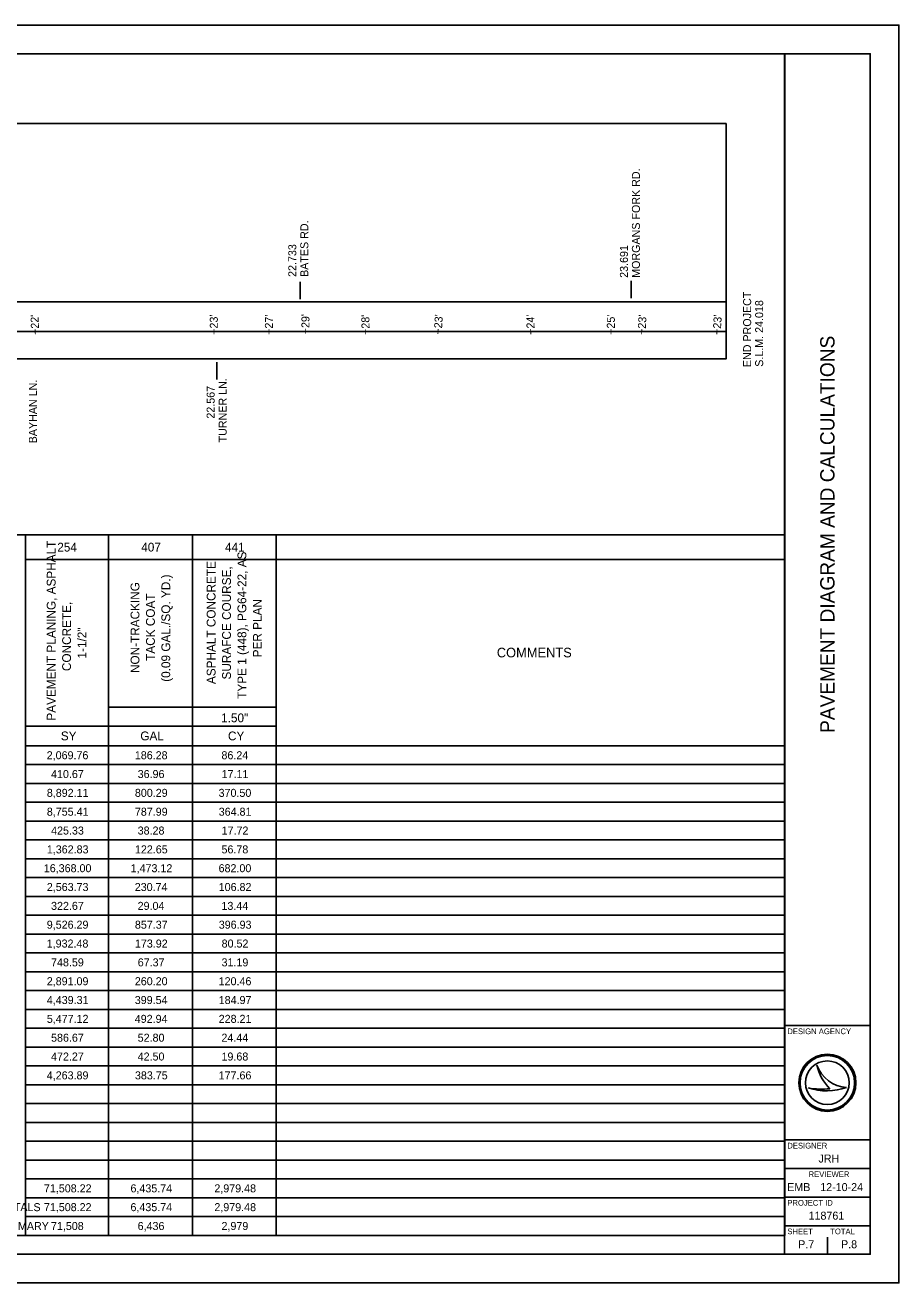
# Model space of a CAD drawing. Extents: x 0 to 34, y 0 to 22.
# Drawn here: x 18.72 to 34, y 0 to 22 of the extents above; entities that cross this region are included whole.
import ezdxf

# ---------------------------------------------------------------- set-up
doc = ezdxf.new("R2010")
doc.units = 0
for name, color, linetype in [('Default', 7, 'Continuous'), ('SH_Border', 7, 'Continuous'), ('SH_Cut_Line', 7, 'Continuous'), ('SH_Data', 7, 'Continuous'), ('SH_Text', 7, 'Continuous')]:
    doc.layers.add(name, color=color, linetype=linetype)

msp = doc.modelspace()

# ---------------------------------------------------------------- linework, layer by layer
at = {"layer": 'Default'}
for p, q in [((1.5, 21.5), (32.004, 21.5)), ((32.004, 21.5), (32.004, 0.829)), ((2.554, 20.282), (30.979, 20.282)), ((30.979, 19.16), (30.979, 20.282)), ((30.979, 20.282), (30.979, 17.16)), ((23.527, 17.209), (23.527, 17.509)), ((29.316, 17.225), (29.316, 17.525)), ((30.979, 17.16), (30.979, 16.161)), ((2.564, 16.643), (30.989, 16.64)), ((22.072, 16.104), (22.072, 15.804)), ((15.802, 13.084), (18.723, 13.084)), ((18.701, 13.084), (32.004, 13.084)), ((18.723, 13.084), (18.723, 0.829)), ((20.178, 13.084), (20.178, 0.829)), ((21.644, 13.084), (21.644, 0.829)), ((23.109, 13.084), (23.109, 0.829)), ((18.723, 12.655), (32.004, 12.655)), ((20.178, 10.069), (23.109, 10.069)), ((18.723, 9.74), (23.109, 9.74)), ((18.723, 9.394), (32.004, 9.394)), ((18.723, 9.065), (32.004, 9.065)), ((18.723, 8.735), (32.004, 8.735)), ((18.723, 8.406), (32.004, 8.406)), ((18.723, 8.076), (32.004, 8.076)), ((18.723, 7.747), (32.004, 7.747)), ((18.723, 7.418), (32.004, 7.418)), ((18.723, 7.088), (32.004, 7.088)), ((18.723, 6.759), (32.004, 6.759)), ((18.723, 6.429), (32.004, 6.429)), ((18.723, 6.1), (32.004, 6.1)), ((18.723, 5.771), (32.004, 5.771)), ((18.723, 5.441), (32.004, 5.441)), ((18.723, 5.112), (32.004, 5.112)), ((18.723, 4.782), (32.004, 4.782)), ((18.723, 4.453), (32.004, 4.453)), ((18.723, 4.124), (32.004, 4.124)), ((18.723, 3.794), (32.004, 3.794)), ((18.723, 3.465), (32.004, 3.465)), ((18.723, 3.135), (32.004, 3.135)), ((18.723, 2.806), (32.004, 2.806)), ((18.723, 2.476), (32.004, 2.476)), ((18.723, 2.147), (32.004, 2.147)), ((18.723, 1.818), (32.004, 1.818)), ((18.723, 1.488), (32.004, 1.488)), ((18.723, 1.159), (32.004, 1.159)), ((1.5, 0.829), (18.723, 0.829)), ((18.701, 0.829), (32.004, 0.829))]:
    msp.add_line(p, q, dxfattribs=at)
msp.add_lwpolyline([(30.979, 17.16), (2.554, 17.16), (2.554, 16.161), (30.979, 16.161)], close=True, dxfattribs=at)
at = {"layer": 'SH_Border'}
for p, q in [((32, 0.5), (32, 21.5)), ((32, 4.5), (33.5, 4.5)), ((32, 2.5), (33.5, 2.5)), ((32, 2), (33.5, 2)), ((32, 1.5), (33.5, 1.5)), ((32, 1), (33.5, 1))]:
    msp.add_line(p, q, dxfattribs=at)
msp.add_lwpolyline([(1.5, 21.5), (33.5, 21.5), (33.5, 0.5), (1.5, 0.5)], close=True, dxfattribs=at)
at = {"layer": 'SH_Cut_Line'}
msp.add_lwpolyline([(0, 0), (34, 0), (34, 22), (0, 22)], close=True, dxfattribs=at)
at = {"layer": 'SH_Data'}
for p, q in [((32.567, 3.81), (32.567, 3.81)), ((32.417, 3.41), (32.417, 3.41)), ((32.75, 3.5), (32.75, 3.5)), ((33.087, 3.419), (33.087, 3.419)), ((32.375, 0.675), (32.375, 0.675)), ((32.75, 0.5), (32.75, 0.8))]:
    msp.add_line(p, q, dxfattribs=at)
for radius in [0.5, 0.477, 0.477, 0.382]:
    msp.add_circle((32.75, 3.5), radius, dxfattribs=at)
for centre, radius, start, end in [((33.116, 3.998), 0.58, 198.9257, 198.9319), ((33.347, 3.97), 0.796, 191.6379, 191.6421), ((33.116, 3.998), 0.58, 198.9319, 267.1657), ((33.347, 3.97), 0.796, 191.6421, 226.0947), ((32.739, 4.37), 1.013, 251.4576, 290.0832), ((32.648, 4.654), 1.266, 259.4964, 259.4995), ((32.739, 4.37), 1.013, 251.4527, 251.4576), ((32.648, 4.654), 1.266, 259.4995, 276.6672)]:
    msp.add_arc(centre, radius, start, end, dxfattribs=at)
at = {"layer": 'SH_Text'}
for p, q in [((2.564, 16.643), (30.989, 16.64)), ((2.554, 16.161), (30.979, 16.161))]:
    msp.add_line(p, q, dxfattribs=at)

# ---------------------------------------------------------------- texts
at = {"layer": 'Default'}
for s, height, rotation, p in [('MORGANS FORK RD.', 0.14, 90, (29.472, 17.58)), ('BATES RD.', 0.14, 90, (23.672, 17.596)), ('22.733', 0.14, 90, (23.462, 17.596)), ('23.691', 0.14, 90, (29.262, 17.58)), ('END PROJECT', 0.14, 90, (31.417, 16.018)), ('S.L.M. 24.018', 0.14, 90, (31.627, 16.024)), ("+22'", 0.14, 91.951, (18.965, 16.584)), ("+23'", 0.14, 90, (22.089, 16.584)), ("+27'", 0.14, 89.232, (23.051, 16.582)), ("+29'", 0.14, 90, (23.692, 16.593)), ("+28'", 0.14, 90.7201, (24.744, 16.582)), ("+23'", 0.14, 86.6363, (26.005, 16.583)), ("+24'", 0.14, 91.2491, (27.631, 16.586)), ("+25'", 0.14, 89.976, (29.033, 16.583)), ("+23'", 0.14, 86.6363, (29.568, 16.578)), ("+23'", 0.14, 86.6363, (30.883, 16.578)), ('BAYHAN LN.', 0.14, 90, (18.925, 14.685)), ('        22.567', 0.14, 90, (22.034, 14.701)), ('TURNER LN.', 0.14, 90, (22.244, 14.701)), ('PAVEMENT PLANING, ASPHALT ', 0.154, 90, (19.252, 9.835)), ('TYPE 1 (448), PG64-22, AS ', 0.154, 90, (22.588, 10.216)), ('ASPHALT CONCRETE ', 0.154, 90, (22.049, 10.474)), ('(0.09 GAL./SQ. YD.)', 0.154, 90, (21.257, 10.514)), ('SURAFCE COURSE, ', 0.154, 90, (22.319, 10.554)), ('NON-TRACKING ', 0.154, 90, (20.718, 10.667)), ('CONCRETE, ', 0.154, 90, (19.522, 10.701)), ('TACK COAT', 0.154, 90, (20.988, 10.88)), ('PER PLAN', 0.154, 90, (22.858, 10.942)), ('1-1/2"', 0.154, 90, (19.791, 10.921))]:
    msp.add_text(s, height=height, rotation=rotation, dxfattribs=at).set_placement(p)
for s, height, p in [('254', 0.154, (19.282, 12.792)), ('407', 0.154, (20.75, 12.792)), ('441', 0.154, (22.216, 12.792)), ('COMMENTS', 0.168, (26.969, 10.941)), ('1.50"', 0.154, (22.147, 9.806)), ('SY', 0.154, (19.344, 9.49)), ('GAL', 0.154, (20.734, 9.49)), ('CY', 0.154, (22.267, 9.49)), ('2,069.76', 0.14, (19.097, 9.159)), ('186.28', 0.14, (20.638, 9.159)), ('86.24', 0.14, (22.153, 9.159)), ('410.67', 0.14, (19.173, 8.83)), ('36.96', 0.14, (20.688, 8.83)), ('17.11', 0.14, (22.156, 8.83)), ('8,892.11', 0.14, (19.099, 8.501)), ('800.29', 0.14, (20.639, 8.501)), ('370.50', 0.14, (22.103, 8.501)), ('8,755.41', 0.14, (19.099, 8.171)), ('787.99', 0.14, (20.639, 8.171)), ('364.81', 0.14, (22.105, 8.171)), ('425.33', 0.14, (19.174, 7.842)), ('38.28', 0.14, (20.688, 7.842)), ('17.72', 0.14, (22.156, 7.842)), ('1,362.83', 0.14, (19.099, 7.512)), ('122.65', 0.14, (20.64, 7.512)), ('56.78', 0.14, (22.154, 7.512)), ('16,368.00', 0.14, (19.046, 7.183)), ('1,473.12', 0.14, (20.565, 7.183)), ('682.00', 0.14, (22.103, 7.183)), ('2,563.73', 0.14, (19.099, 6.854)), ('230.74', 0.14, (20.637, 6.854)), ('106.82', 0.14, (22.105, 6.854)), ('322.67', 0.14, (19.173, 6.524)), ('29.04', 0.14, (20.687, 6.524)), ('13.44', 0.14, (22.153, 6.524)), ('9,526.29', 0.14, (19.098, 6.195)), ('857.37', 0.14, (20.639, 6.195)), ('396.93', 0.14, (22.106, 6.195)), ('1,932.48', 0.14, (19.097, 5.865)), ('173.92', 0.14, (20.64, 5.865)), ('80.52', 0.14, (22.156, 5.865)), ('748.59', 0.14, (19.173, 5.536)), ('67.37', 0.14, (20.689, 5.536)), ('31.19', 0.14, (22.155, 5.536)), ('2,891.09', 0.14, (19.098, 5.206)), ('260.20', 0.14, (20.638, 5.206)), ('120.46', 0.14, (22.104, 5.206)), ('4,439.31', 0.14, (19.099, 4.877)), ('399.54', 0.14, (20.637, 4.877)), ('184.97', 0.14, (22.105, 4.877)), ('5,477.12', 0.14, (19.099, 4.548)), ('492.94', 0.14, (20.637, 4.548)), ('228.21', 0.14, (22.105, 4.548)), ('586.67', 0.14, (19.173, 4.218)), ('52.80', 0.14, (20.688, 4.218)), ('24.44', 0.14, (22.153, 4.218)), ('472.27', 0.14, (19.173, 3.889)), ('42.50', 0.14, (20.688, 3.889)), ('19.68', 0.14, (22.154, 3.889)), ('4,263.89', 0.14, (19.098, 3.559)), ('383.75', 0.14, (20.64, 3.559)), ('177.66', 0.14, (22.104, 3.559)), ('71,508.22', 0.14, (19.048, 1.583)), ('6,435.74', 0.14, (20.562, 1.583)), ('2,979.48', 0.14, (22.029, 1.583)), ('THIS SHEET TOTALS', 0.14, (17.108, 1.254)), ('71,508.22', 0.14, (19.048, 1.254)), ('6,435.74', 0.14, (20.562, 1.254)), ('2,979.48', 0.14, (22.029, 1.254)), ('TOTALS CARRIED TO GENERAL SUMMARY', 0.14, (15.244, 0.924)), ('71,508', 0.14, (19.171, 0.924)), ('6,436', 0.14, (20.687, 0.924)), ('2,979', 0.14, (22.154, 0.924))]:
    msp.add_text(s, height=height, dxfattribs=at).set_placement(p)
at = {"layer": 'SH_Data'}
msp.add_text('PAVEMENT DIAGRAM AND CALCULATIONS', height=0.25, rotation=90, dxfattribs=at).set_placement((32.875, 9.62))
for s, height, p in [('DESIGN AGENCY', 0.1, (32.05, 4.35)), ('DESIGNER', 0.1, (32.05, 2.35)), ('JRH', 0.14, (32.595, 2.105)), ('REVIEWER', 0.1, (32.422, 1.85)), ('EMB', 0.14, (32.047, 1.605)), ('12-10-24', 0.14, (32.625, 1.605)), ('PROJECT ID', 0.1, (32.05, 1.35)), ('118761', 0.14, (32.421, 1.105)), ('SHEET', 0.1, (32.05, 0.85)), ('TOTAL', 0.1, (32.8, 0.85)), ('P.7', 0.14, (32.239, 0.605)), ('P.8', 0.14, (32.989, 0.605))]:
    msp.add_text(s, height=height, dxfattribs=at).set_placement(p)

doc.saveas('drawing.dxf')
